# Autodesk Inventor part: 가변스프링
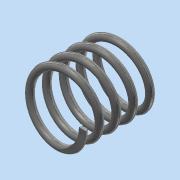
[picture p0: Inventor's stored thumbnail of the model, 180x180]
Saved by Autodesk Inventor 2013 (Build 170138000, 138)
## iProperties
Created: 2015-03
Part Number: 가변스프링
Material: 강철, 탄소
Document SubType Name: Modeling
Designer: Administrator
Density: 7.87 g/cm^3
Mass: 47.9946 g
Surface Area: 62.0026 cm^2
Volume: 6.09842 cm^3
Author: Administrator
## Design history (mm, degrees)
sketch "스케치1"
  geometry: L1 (0, 0)-(0, 43.5); L2 (0, 43.5)-(17.5, 43.5); L3 (17.5, 43.5)-(17.5, 0); L4 (17.5, 0)-(0, 0); C1 r 2 at (17.5, 0)
  constraints: 8 end point, 2 perpendicular, 1 centre point, 1 coincident, 1 parallel, 1 vertical
  dimensions: "d0" = 43.5 distance of L1.start L1.end (derived); "d1" = 4 diameter of C1; "d2" = 35 diameter of C1.centre L1
feature "코일1" sketch "스케치1" pitch "d3" = 10; turns "d5" = 4.5; dims "d4" = 43.5 (= d0), "d6" = 0, angle "d7" = 90 deg, angle "d8" = 90 deg, "d9" = 0, "d10" = 0
sketch "스케치2"
  geometry: L1 (0, 20)-(43.5, 20); L2 (43.5, 20)-(43.5, -20); L3 (43.5, -20)-(0, -20); L4 (0, -20)-(0, 20); 2 further points
  constraints: 8 end point, 2 parallel, 1 coincident, 1 horizontal, 1 midpoint, 1 perpendicular
  dimensions: "d11" = 40 distance of L1.end L2.end; "d13" = 43.5 distance of L1.start L1.end (derived)
extrude "돌출1" sketch "스케치2" stored distance "d14" = 40; taper "d15" = 0 deg
node "솔리드1"
